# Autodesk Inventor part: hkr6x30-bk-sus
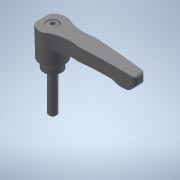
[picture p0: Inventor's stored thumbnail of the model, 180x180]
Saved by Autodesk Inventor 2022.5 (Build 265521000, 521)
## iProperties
Created: 2017-09
Part Number: hkr6x30-bk-sus
Material: 一般
Document SubType Name: Modeling
Designer: imaocorp
Density: 1 g/cm^3
Appearance: 既定
Author: imaocorp
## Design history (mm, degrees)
node "hkr6x30-bk-sus.x_t1"
node "hkr6x30-bk-sus"
node "Base1"
